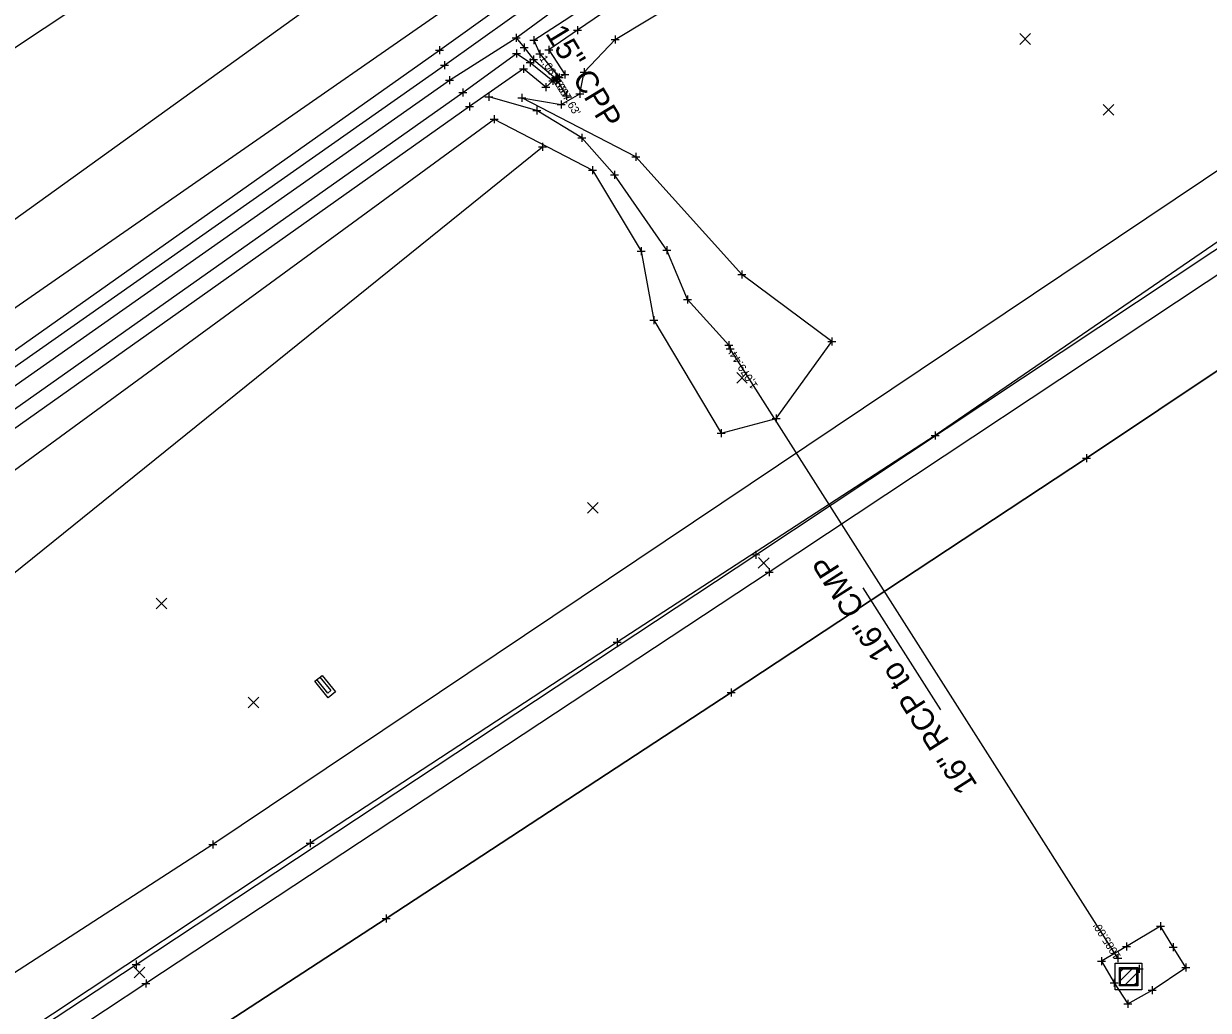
# Model space of a CAD drawing. Extents: x 142461 to 147261, y 511126 to 514697.
# Drawn here: x 143831 to 143978.9, y 512598.5 to 512721.7 of the extents above; entities that cross this region are included whole.
import ezdxf

# ---------------------------------------------------------------- set-up
doc = ezdxf.new("R2010")
doc.units = 0
for name, color, linetype in [('DR_X_Cells', 7, 'Continuous'), ('DR_X_Ditch', 7, 'Continuous'), ('DR_X_Elev_Flow', 7, 'Continuous'), ('DR_X_Storm_Sewer', 7, 'Continuous'), ('DR_X_Text', 7, 'Continuous'), ('GK_Drainage_Nodes', 7, 'Continuous'), ('PM_X_Surveyed_Line', 7, 'Continuous'), ('PV_X_EOP', 7, 'Continuous'), ('RD_X_Concrete_Pad', 7, 'Continuous'), ('RD_X_Fence', 7, 'Continuous'), ('RD_X_GR_Lt', 7, 'Continuous'), ('SC_Scratch1', 7, 'Continuous'), ('SV_X_Break_Lines', 7, 'Continuous'), ('SV_X_Original_Ground', 7, 'Continuous'), ('SV_X_Random_Point', 7, 'Continuous'), ('SV_X_Shot_Marker', 7, 'Continuous'), ('SV_X_Toe_of_Slope', 7, 'Continuous'), ('SV_X_Top_of_Bank', 7, 'Continuous'), ('VG_X_Tree_Line_Lt', 7, 'Continuous')]:
    doc.layers.add(name, color=color, linetype=linetype)

msp = doc.modelspace()

# ---------------------------------------------------------------- linework, layer by layer
at = {"layer": 'DR_X_Cells'}
for p, q in [((143868.96, 512638.14), (143867.59, 512639.82)), ((143867.97, 512640.14), (143869.34, 512638.46)), ((143869.34, 512638.46), (143868.96, 512638.14)), ((143967.83, 512602.12), (143969.59, 512603.88)), ((143967.83, 512603.25), (143968.46, 512603.88)), ((143968.43, 512601.59), (143970.12, 512603.28)), ((143969.56, 512601.59), (143970.12, 512602.15))]:
    msp.add_line(p, q, dxfattribs=at)
for points in [[(143869.01, 512637.54), (143867.33, 512639.61), (143868.23, 512640.35), (143869.92, 512638.28)], [(143967.31, 512604.4), (143970.64, 512604.4), (143970.64, 512601.07), (143967.31, 512601.07)], [(143967.83, 512603.88), (143970.12, 512603.88), (143970.12, 512601.59), (143967.83, 512601.59)], [(143967.97, 512603.73), (143969.97, 512603.73), (143969.97, 512601.73), (143967.97, 512601.73)]]:
    msp.add_lwpolyline(points, close=True, dxfattribs=at)
at = {"layer": 'DR_X_Ditch'}
for points in [[(143682.01, 512580.83), (143685.31, 512583.54), (143724.15, 512607.74), (143773.83, 512639.38), (143817.77, 512668.05), (143884.16, 512714.69), (143892.48, 512719.95), (143898.08, 512724.09), (143935.1, 512749.47), (143987.04, 512774.9), (144007.03, 512781.4), (144021.53, 512785.31), (144053.35, 512790.59), (144090.66, 512791.74), (144100.85, 512793.04), (144110.39, 512797.23), (144133.59, 512811.55), (144134.7, 512812.84), (144148.77, 512821.51)], [(143892.48, 512719.95), (143893.49, 512718.74), (143894.66, 512717.26), (143897.45, 512714.9)], [(143919.06, 512681.6), (143913.86, 512687.27), (143911.31, 512693.44), (143904.75, 512702.86), (143900.68, 512707.46), (143895.04, 512710.87), (143889.08, 512712.61)]]:
    msp.add_lwpolyline(points, dxfattribs=at)
at = {"layer": 'DR_X_Elev_Flow'}
for p, q in [((143898.26, 512712.73), (143899.26, 512712.73)), ((143898.76, 512713.23), (143898.76, 512712.23)), ((143898.76, 512712.73), (143898.76, 512712.73)), ((143970.29, 512604.21), (143970.29, 512603.21)), ((143969.79, 512603.71), (143970.79, 512603.71)), ((143970.29, 512603.71), (143970.29, 512603.71))]:
    msp.add_line(p, q, dxfattribs=at)
at = {"layer": 'DR_X_Storm_Sewer'}
for p, q in [((143897.53, 512714.76), (143898.76, 512712.73)), ((143967.63, 512605.04), (143919.19, 512681.13))]:
    msp.add_line(p, q, dxfattribs=at)
at = {"layer": 'DR_X_Text'}
msp.add_line((143935.78, 512651.3), (143945.47, 512636.07), dxfattribs=at)
at = {"layer": 'GK_Drainage_Nodes'}
for p, q in [((143867.78, 512639.98), (143867.78, 512639.98)), ((143869.15, 512638.3), (143869.15, 512638.3)), ((143869.15, 512638.3), (143869.15, 512638.3)), ((143869.15, 512638.3), (143869.15, 512638.3)), ((143869.15, 512638.3), (143869.15, 512638.3)), ((143869.47, 512637.91), (143869.47, 512637.91)), ((143968.97, 512604.4), (143968.97, 512604.4)), ((143967.97, 512602.73), (143967.97, 512602.73)), ((143968.97, 512603.73), (143968.97, 512603.73)), ((143968.97, 512602.73), (143968.97, 512602.73)), ((143968.97, 512602.73), (143968.97, 512602.73)), ((143968.97, 512602.73), (143968.97, 512602.73)), ((143969.97, 512602.73), (143969.97, 512602.73)), ((143968.97, 512601.73), (143968.97, 512601.73)), ((143968.97, 512601.07), (143968.97, 512601.07))]:
    msp.add_line(p, q, dxfattribs=at)
at = {"layer": 'PM_X_Surveyed_Line'}
msp.add_lwpolyline([(144188.92, 512817.39), (144145.08, 512788.07), (144101.53, 512759.11), (144055.26, 512728.55), (144009.03, 512697.74), (143963.71, 512667.48), (143919.34, 512638.22), (143876.24, 512609.98), (143831.96, 512581.14), (143788.16, 512551.89), (143745.95, 512523.22), (143703.35, 512494.8), (143660.81, 512466.6), (143617.97, 512438.11), (143574.3, 512409.08), (143532.89, 512381.73), (143492.85, 512355.06), (143449.68, 512327.04), (143408.89, 512300.85), (143365.54, 512272.99)], dxfattribs=at)
at = {"layer": 'PV_X_EOP'}
for p, q in [((144009.64, 512709.95), (143924.08, 512653.23)), ((143924.08, 512653.23), (143846.24, 512601.89)), ((143846.24, 512601.89), (143764.3, 512547.94))]:
    msp.add_line(p, q, dxfattribs=at)
at = {"layer": 'RD_X_Concrete_Pad'}
for points in [[(143815.82, 512671.05), (143882.89, 512718.41), (143890.64, 512723.97), (143896.06, 512727.67), (143933.01, 512753.29), (143977.06, 512774.83), (143985.38, 512778.07)], [(143981.04, 512767.86), (143937.36, 512746.25), (143900.14, 512720.93), (143896.56, 512718.45), (143898.55, 512715.36), (143897.84, 512715.01), (143897.45, 512714.9), (143897.06, 512714.58), (143896.17, 512713.81), (143893.38, 512716.09), (143886.65, 512711.4), (143820.81, 512664.81)]]:
    msp.add_lwpolyline(points, dxfattribs=at)
msp.add_lwpolyline([(143965.58, 512604.68), (143967.19, 512601.97), (143968.87, 512599.33), (143971.91, 512601.06), (143976.13, 512603.88), (143974.53, 512606.41), (143972.97, 512609.02), (143968.73, 512606.49)], close=True, dxfattribs=at)
at = {"layer": 'RD_X_Fence'}
msp.add_lwpolyline([(146900.86, 514646.23), (146332.42, 514316.7), (145890.39, 514050.56), (145774.93, 514232.06), (145655.09, 514421.49), (144949.64, 513970.2), (144936.36, 513451.75), (144101.94, 512896.99), (144046.01, 512862.62), (143758.01, 512670.87), (143619.22, 512579.24), (143474.12, 512483.15), (143357.83, 512406.57), (143315.36, 512377.21)], dxfattribs=at)
at = {"layer": 'RD_X_GR_Lt'}
msp.add_lwpolyline([(143370.72, 512292.99), (143450.47, 512344.19), (143525.92, 512393.32), (143602.63, 512444.4), (143685.95, 512499.47), (143763.08, 512550.36), (143845.01, 512604.27), (143922.42, 512655.42), (144008.12, 512712.24), (144093.65, 512768.93), (144165.29, 512816.32), (144201.5, 512845.15)], dxfattribs=at)
at = {"layer": 'SV_X_Break_Lines'}
msp.add_lwpolyline([(143347.65, 512339.04), (143386.36, 512362.47), (143418.93, 512386.06), (143465.98, 512416.92), (143501.44, 512440.14), (143543.79, 512469.56), (143600.03, 512507.07), (143642.08, 512535.04), (143688.87, 512563.62), (143738.84, 512593.77), (143782.97, 512622.64), (143829.48, 512652.92), (143895.78, 512706.33)], dxfattribs=at)
at = {"layer": 'SV_X_Original_Ground'}
for points in [[(144027.26, 512848.08), (143982.38, 512795.54), (143924.83, 512765.49), (143882.77, 512735.39), (143807.38, 512681.12), (143758.01, 512670.87), (143714.8, 512624.35), (143670.62, 512596.17)], [(143660.81, 512466.6), (143703.35, 512494.8), (143745.95, 512523.22), (143788.16, 512551.89), (143831.96, 512581.14), (143876.24, 512609.98), (143919.34, 512638.22), (143963.71, 512667.48), (144009.03, 512697.74), (144055.26, 512728.55), (144101.53, 512759.11), (144145.08, 512788.07), (144188.92, 512817.39)]]:
    msp.add_lwpolyline(points, dxfattribs=at)
at = {"layer": 'SV_X_Random_Point'}
for p, q in [((143955.39, 512719.14), (143956.72, 512720.48)), ((143955.39, 512720.48), (143956.72, 512719.14)), ((143965.81, 512710.29), (143967.14, 512711.63)), ((143965.81, 512711.63), (143967.14, 512710.29)), ((143920.02, 512676.86), (143921.35, 512678.19)), ((143920.02, 512678.19), (143921.35, 512676.86)), ((143901.37, 512660.6), (143902.7, 512661.94)), ((143901.37, 512661.94), (143902.7, 512660.6)), ((143922.72, 512653.73), (143924.07, 512655.05)), ((143922.73, 512655.06), (143924.05, 512653.71)), ((143847.51, 512648.66), (143848.84, 512650)), ((143847.51, 512650), (143848.84, 512648.66)), ((143859.01, 512636.31), (143860.34, 512637.64)), ((143859.01, 512637.64), (143860.34, 512636.31)), ((143844.75, 512602.59), (143846.1, 512603.91)), ((143844.77, 512603.92), (143846.09, 512602.57))]:
    msp.add_line(p, q, dxfattribs=at)
at = {"layer": 'SV_X_Shot_Marker'}
for p, q in [((143900.14, 512721.43), (143900.14, 512720.43)), ((143891.98, 512719.95), (143892.98, 512719.95)), ((143891.98, 512719.95), (143892.98, 512719.95)), ((143892.48, 512720.45), (143892.48, 512719.45)), ((143892.48, 512720.45), (143892.48, 512719.45)), ((143892.48, 512719.95), (143892.48, 512719.95)), ((143892.48, 512719.95), (143892.48, 512719.95)), ((143894.2, 512719.65), (143895.2, 512719.65)), ((143894.2, 512719.65), (143895.2, 512719.65)), ((143894.7, 512720.15), (143894.7, 512719.15)), ((143894.7, 512720.15), (143894.7, 512719.15)), ((143894.7, 512719.65), (143894.7, 512719.65)), ((143894.7, 512719.65), (143894.7, 512719.65)), ((143899.64, 512720.93), (143900.64, 512720.93)), ((143900.14, 512720.93), (143900.14, 512720.93)), ((143904.34, 512719.77), (143905.34, 512719.77)), ((143904.84, 512720.27), (143904.84, 512719.27)), ((143904.84, 512719.77), (143904.84, 512719.77)), ((143882.39, 512718.41), (143883.39, 512718.41)), ((143882.89, 512718.91), (143882.89, 512717.91)), ((143882.89, 512718.41), (143882.89, 512718.41)), ((143892.53, 512718.5), (143892.53, 512717.5)), ((143892.53, 512718.5), (143892.53, 512717.5)), ((143892.99, 512718.74), (143893.99, 512718.74)), ((143893.49, 512719.24), (143893.49, 512718.24)), ((143893.49, 512718.74), (143893.49, 512718.74)), ((143895.45, 512718.45), (143895.45, 512717.45)), ((143896.06, 512718.45), (143897.06, 512718.45)), ((143896.56, 512718.95), (143896.56, 512717.95)), ((143896.56, 512718.45), (143896.56, 512718.45)), ((143883.51, 512717.04), (143883.51, 512716.04)), ((143892.03, 512718), (143893.03, 512718)), ((143892.03, 512718), (143893.03, 512718)), ((143892.53, 512718), (143892.53, 512718)), ((143892.53, 512718), (143892.53, 512718)), ((143893.38, 512716.59), (143893.38, 512715.59)), ((143893.73, 512716.88), (143894.73, 512716.88)), ((143894.16, 512717.26), (143895.16, 512717.26)), ((143894.23, 512717.38), (143894.23, 512716.38)), ((143894.23, 512716.88), (143894.23, 512716.88)), ((143894.66, 512717.76), (143894.66, 512716.76)), ((143894.66, 512717.26), (143894.66, 512717.26)), ((143894.95, 512717.95), (143895.95, 512717.95)), ((143895.45, 512717.95), (143895.45, 512717.95)), ((143883.01, 512716.54), (143884.01, 512716.54)), ((143883.51, 512716.54), (143883.51, 512716.54)), ((143884.16, 512715.19), (143884.16, 512714.19)), ((143892.88, 512716.09), (143893.88, 512716.09)), ((143893.38, 512716.09), (143893.38, 512716.09)), ((143897.45, 512715.4), (143897.45, 512714.4)), ((143897.45, 512715.4), (143897.45, 512714.4)), ((143897.53, 512715.26), (143897.53, 512714.26)), ((143897.84, 512715.51), (143897.84, 512714.51)), ((143897.84, 512715.51), (143897.84, 512714.51)), ((143898.05, 512715.36), (143899.05, 512715.36)), ((143898.55, 512715.86), (143898.55, 512714.86)), ((143898.55, 512715.36), (143898.55, 512715.36)), ((143900.49, 512715.66), (143901.49, 512715.66)), ((143900.99, 512716.16), (143900.99, 512715.16)), ((143900.99, 512715.66), (143900.99, 512715.66)), ((143883.66, 512714.69), (143884.66, 512714.69)), ((143884.16, 512714.69), (143884.16, 512714.69)), ((143885.82, 512713.64), (143885.82, 512712.64)), ((143895.67, 512713.81), (143896.67, 512713.81)), ((143896.17, 512714.31), (143896.17, 512713.31)), ((143896.17, 512713.81), (143896.17, 512713.81)), ((143896.56, 512714.58), (143897.56, 512714.58)), ((143896.56, 512714.58), (143897.56, 512714.58)), ((143896.95, 512714.9), (143897.95, 512714.9)), ((143896.95, 512714.9), (143897.95, 512714.9)), ((143897.03, 512714.76), (143898.03, 512714.76)), ((143897.06, 512715.08), (143897.06, 512714.08)), ((143897.06, 512715.08), (143897.06, 512714.08)), ((143897.06, 512714.58), (143897.06, 512714.58)), ((143897.06, 512714.58), (143897.06, 512714.58)), ((143897.34, 512715.01), (143898.34, 512715.01)), ((143897.34, 512715.01), (143898.34, 512715.01)), ((143897.45, 512714.9), (143897.45, 512714.9)), ((143897.45, 512714.9), (143897.45, 512714.9)), ((143897.53, 512714.76), (143897.53, 512714.76)), ((143897.84, 512715.01), (143897.84, 512715.01)), ((143897.84, 512715.01), (143897.84, 512715.01)), ((143885.32, 512713.14), (143886.32, 512713.14)), ((143885.82, 512713.14), (143885.82, 512713.14)), ((143888.58, 512712.61), (143889.58, 512712.61)), ((143889.08, 512713.11), (143889.08, 512712.11)), ((143889.08, 512712.61), (143889.08, 512712.61)), ((143892.68, 512712.46), (143893.68, 512712.46)), ((143892.68, 512712.46), (143893.68, 512712.46)), ((143893.18, 512712.96), (143893.18, 512711.96)), ((143893.18, 512712.96), (143893.18, 512711.96)), ((143893.18, 512712.46), (143893.18, 512712.46)), ((143893.18, 512712.46), (143893.18, 512712.46)), ((143899.95, 512712.95), (143900.95, 512712.95)), ((143900.45, 512713.45), (143900.45, 512712.45)), ((143900.45, 512712.95), (143900.45, 512712.95)), ((143886.15, 512711.4), (143887.15, 512711.4)), ((143886.65, 512711.9), (143886.65, 512710.9)), ((143886.65, 512711.4), (143886.65, 512711.4)), ((143894.54, 512710.87), (143895.54, 512710.87)), ((143895.04, 512711.37), (143895.04, 512710.37)), ((143895.04, 512710.87), (143895.04, 512710.87)), ((143897.61, 512711.65), (143898.61, 512711.65)), ((143898.11, 512712.15), (143898.11, 512711.15)), ((143898.11, 512711.65), (143898.11, 512711.65)), ((143889.24, 512709.8), (143890.24, 512709.8)), ((143889.24, 512709.8), (143890.24, 512709.8)), ((143889.74, 512710.3), (143889.74, 512709.3)), ((143889.74, 512710.3), (143889.74, 512709.3)), ((143889.74, 512709.8), (143889.74, 512709.8)), ((143889.74, 512709.8), (143889.74, 512709.8)), ((143900.68, 512707.96), (143900.68, 512706.96)), ((143895.28, 512706.33), (143896.28, 512706.33)), ((143895.78, 512706.83), (143895.78, 512705.83)), ((143895.78, 512706.33), (143895.78, 512706.33)), ((143900.18, 512707.46), (143901.18, 512707.46)), ((143900.68, 512707.46), (143900.68, 512707.46)), ((143906.92, 512705.11), (143907.92, 512705.11)), ((143907.42, 512705.61), (143907.42, 512704.61)), ((143907.42, 512705.11), (143907.42, 512705.11)), ((143901.5, 512703.45), (143902.5, 512703.45)), ((143902, 512703.95), (143902, 512702.95)), ((143902, 512703.45), (143902, 512703.45)), ((143904.75, 512703.36), (143904.75, 512702.36)), ((143904.25, 512702.86), (143905.25, 512702.86)), ((143904.75, 512702.86), (143904.75, 512702.86)), ((143907.59, 512693.32), (143908.59, 512693.32)), ((143908.09, 512693.82), (143908.09, 512692.82)), ((143908.09, 512693.32), (143908.09, 512693.32)), ((143910.81, 512693.44), (143911.81, 512693.44)), ((143911.31, 512693.94), (143911.31, 512692.94)), ((143911.31, 512693.44), (143911.31, 512693.44)), ((143920.18, 512690.41), (143921.18, 512690.41)), ((143920.68, 512690.91), (143920.68, 512689.91)), ((143920.68, 512690.41), (143920.68, 512690.41)), ((143913.36, 512687.27), (143914.36, 512687.27)), ((143913.86, 512687.77), (143913.86, 512686.77)), ((143913.86, 512687.27), (143913.86, 512687.27)), ((143909.19, 512684.71), (143910.19, 512684.71)), ((143909.69, 512685.21), (143909.69, 512684.21)), ((143909.69, 512684.71), (143909.69, 512684.71)), ((143918.56, 512681.6), (143919.56, 512681.6)), ((143918.69, 512681.13), (143919.69, 512681.13)), ((143919.06, 512682.1), (143919.06, 512681.1)), ((143919.06, 512681.6), (143919.06, 512681.6)), ((143919.19, 512681.63), (143919.19, 512680.63)), ((143919.19, 512681.13), (143919.19, 512681.13)), ((143931.41, 512682.05), (143932.41, 512682.05)), ((143931.91, 512682.55), (143931.91, 512681.55)), ((143931.91, 512682.05), (143931.91, 512682.05)), ((143924.46, 512672.44), (143925.46, 512672.44)), ((143924.96, 512672.94), (143924.96, 512671.94)), ((143924.96, 512672.44), (143924.96, 512672.44)), ((143918.07, 512671.11), (143918.07, 512670.11)), ((143944.81, 512670.79), (143944.81, 512669.79)), ((143917.57, 512670.61), (143918.57, 512670.61)), ((143918.07, 512670.61), (143918.07, 512670.61)), ((143944.31, 512670.29), (143945.31, 512670.29)), ((143944.81, 512670.29), (143944.81, 512670.29)), ((143963.71, 512667.98), (143963.71, 512666.98)), ((143963.21, 512667.48), (143964.21, 512667.48)), ((143963.71, 512667.48), (143963.71, 512667.48)), ((143921.92, 512655.43), (143922.92, 512655.42)), ((143922.42, 512655.92), (143922.41, 512654.92)), ((143922.42, 512655.42), (143922.42, 512655.42)), ((143923.58, 512653.23), (143924.58, 512653.22)), ((143924.09, 512653.73), (143924.08, 512652.73)), ((143924.08, 512653.23), (143924.08, 512653.23)), ((143904.59, 512644.48), (143905.59, 512644.48)), ((143905.09, 512644.98), (143905.09, 512643.98)), ((143905.09, 512644.48), (143905.09, 512644.48)), ((143918.84, 512638.22), (143919.84, 512638.22)), ((143919.34, 512638.72), (143919.34, 512637.72)), ((143919.34, 512638.22), (143919.34, 512638.22)), ((143854.08, 512619.23), (143855.08, 512619.22)), ((143854.59, 512619.72), (143854.58, 512618.72)), ((143854.58, 512619.22), (143854.58, 512619.22)), ((143866.26, 512619.42), (143867.26, 512619.42)), ((143866.76, 512619.92), (143866.76, 512618.92)), ((143866.76, 512619.42), (143866.76, 512619.42)), ((143876.24, 512610.48), (143876.24, 512609.48)), ((143875.74, 512609.98), (143876.74, 512609.98)), ((143876.24, 512609.98), (143876.24, 512609.98)), ((143972.47, 512609.02), (143973.47, 512609.02)), ((143972.97, 512609.52), (143972.97, 512608.52)), ((143972.97, 512609.02), (143972.97, 512609.02)), ((143968.23, 512606.49), (143969.23, 512606.49)), ((143968.73, 512606.99), (143968.73, 512605.99)), ((143968.73, 512606.49), (143968.73, 512606.49)), ((143974.03, 512606.41), (143975.03, 512606.41)), ((143974.53, 512606.91), (143974.53, 512605.91)), ((143974.53, 512606.41), (143974.53, 512606.41)), ((143844.51, 512604.27), (143845.51, 512604.26)), ((143845.01, 512604.77), (143845, 512603.77)), ((143845.01, 512604.27), (143845.01, 512604.27)), ((143965.08, 512604.68), (143966.08, 512604.68)), ((143965.58, 512605.18), (143965.58, 512604.18)), ((143965.58, 512604.68), (143965.58, 512604.68)), ((143967.13, 512605.04), (143968.13, 512605.04)), ((143967.63, 512605.54), (143967.63, 512604.54)), ((143967.63, 512605.04), (143967.63, 512605.04)), ((143976.13, 512604.38), (143976.13, 512603.38)), ((143975.63, 512603.88), (143976.63, 512603.88)), ((143976.13, 512603.88), (143976.13, 512603.88)), ((143845.74, 512601.9), (143846.74, 512601.88)), ((143846.25, 512602.39), (143846.24, 512601.39)), ((143846.24, 512601.89), (143846.24, 512601.89)), ((143966.69, 512601.97), (143967.69, 512601.97)), ((143967.19, 512602.47), (143967.19, 512601.47)), ((143967.19, 512601.97), (143967.19, 512601.97)), ((143971.91, 512601.56), (143971.91, 512600.56)), ((143968.87, 512599.83), (143968.87, 512598.83)), ((143971.41, 512601.06), (143972.41, 512601.06)), ((143971.91, 512601.06), (143971.91, 512601.06)), ((143968.37, 512599.33), (143969.37, 512599.33)), ((143968.87, 512599.33), (143968.87, 512599.33))]:
    msp.add_line(p, q, dxfattribs=at)
at = {"layer": 'SV_X_Toe_of_Slope'}
for points in [[(143680.34, 512582.26), (143684.09, 512585.37), (143722.93, 512609.29), (143773.21, 512641.03), (143816.4, 512669.47), (143883.51, 512716.54), (143891.92, 512722.52), (143896.92, 512726.02), (143934.1, 512751.38), (143977.9, 512773.22), (143985.91, 512777.21), (144006.46, 512783.41), (144020.81, 512787.3), (144052.82, 512792.52), (144090.54, 512793.49), (144100.23, 512795.22), (144109.97, 512798.83), (144132.21, 512813.66)], [(143894.7, 512719.65), (143899.2, 512722.58), (143935.78, 512747.75), (143980.08, 512769.36), (143987.67, 512773.67), (144007.51, 512779.7), (144022.09, 512783.4), (144053.76, 512788.55), (144090.69, 512789.34), (144101.49, 512791.12), (144111.22, 512795.5), (144134.69, 512810.44)], [(143894.7, 512719.65), (143895.45, 512717.95), (143897.84, 512715.01)], [(143337.74, 512354.13), (143373.83, 512379.61), (143409.82, 512401.88), (143456.93, 512434.15), (143491.83, 512455), (143537.93, 512485.66), (143588.71, 512521.29), (143628.11, 512542.92), (143683.37, 512578.57), (143686.38, 512581.99), (143724.8, 512605.63), (143775.5, 512637.43), (143819.58, 512666.39), (143885.82, 512713.14), (143892.53, 512718)], [(143892.53, 512718), (143894.23, 512716.88), (143897.06, 512714.58)]]:
    msp.add_lwpolyline(points, dxfattribs=at)
at = {"layer": 'SV_X_Top_of_Bank'}
for points in [[(144187.53, 512836.11), (144149.1, 512812.16), (144114.5, 512784.04), (144076.54, 512758.94), (144065.1, 512752.01), (144055.17, 512745.7), (144018.12, 512720.44), (143980.94, 512695.06), (143944.81, 512670.29), (143905.09, 512644.48), (143866.76, 512619.42), (143829.97, 512595), (143792.48, 512569.79), (143751.87, 512542.92), (143712.15, 512516.06), (143675.85, 512495.35), (143654.21, 512481.3), (143619.5, 512453.21), (143581.89, 512430.02), (143540.43, 512402.85), (143499.04, 512373.78), (143457.05, 512347.22), (143413.81, 512319.09), (143368.71, 512290.7)], [(143333.29, 512365.85), (143365.36, 512390.63), (143401.8, 512414.01), (143448.55, 512445.14), (143485.12, 512467.1), (143528.57, 512495.67), (143580.79, 512531.17), (143621.7, 512555.49), (143675.7, 512590.65), (143720.06, 512612.77), (143770.19, 512646.9), (143813.33, 512674.82), (143929.82, 512755.67), (143985.7, 512783.42), (144019.42, 512791.32), (144052.32, 512796.47), (144090.32, 512797.2), (144099.95, 512798.87), (144108.12, 512801.61)], [(143631.05, 512537.41), (143686.72, 512568.48), (143729.38, 512601.95), (143779.9, 512631.14), (143823.59, 512661.43), (143889.74, 512709.8), (143902, 512703.45), (143908.09, 512693.32), (143909.69, 512684.71), (143918.07, 512670.61), (143924.96, 512672.44), (143931.91, 512682.05), (143920.68, 512690.41), (143907.42, 512705.11), (143893.18, 512712.46), (143898.11, 512711.65), (143900.45, 512712.95), (143900.99, 512715.66), (143904.84, 512719.77), (143989.5, 512770.73), (144023.94, 512778.32), (144055.43, 512785.21), (144092.49, 512785.17), (144103.37, 512787.86)]]:
    msp.add_lwpolyline(points, dxfattribs=at)
at = {"layer": 'VG_X_Tree_Line_Lt'}
msp.add_lwpolyline([(144949.64, 513970.2), (144940.67, 513403.38), (144869.27, 513342.8), (144835.43, 513285.24), (144755.87, 513265.97), (144717.47, 513211.11), (144425.23, 513005.37), (144089.54, 512783), (144041.9, 512744.84), (143854.58, 512619.22), (143367, 512303.84)], dxfattribs=at)

# ---------------------------------------------------------------- texts
at = {"layer": 'DR_X_Text'}
for s, rotation, p in [('15" CPP', 301.1579, (143896.06, 512720.52)), ('16" RCP to 16" CMP', 122.4805, (143950.17, 512626.65))]:
    msp.add_text(s, height=2.8, rotation=rotation, dxfattribs=at).set_placement(p)
at = {"layer": 'SC_Scratch1'}
for s, rotation, p in [("1,067.63'", 301.1579, (143895.34, 512717.41)), ("1067.63'", 301.1579, (143897.1, 512714.5)), ("1,079.44'", 122.4805, (143922.72, 512676.52)), ("1085.80'", 122.4805, (143968.05, 512605.31))]:
    msp.add_text(s, height=1, rotation=rotation, dxfattribs=at).set_placement(p)

doc.saveas('drawing.dxf')
